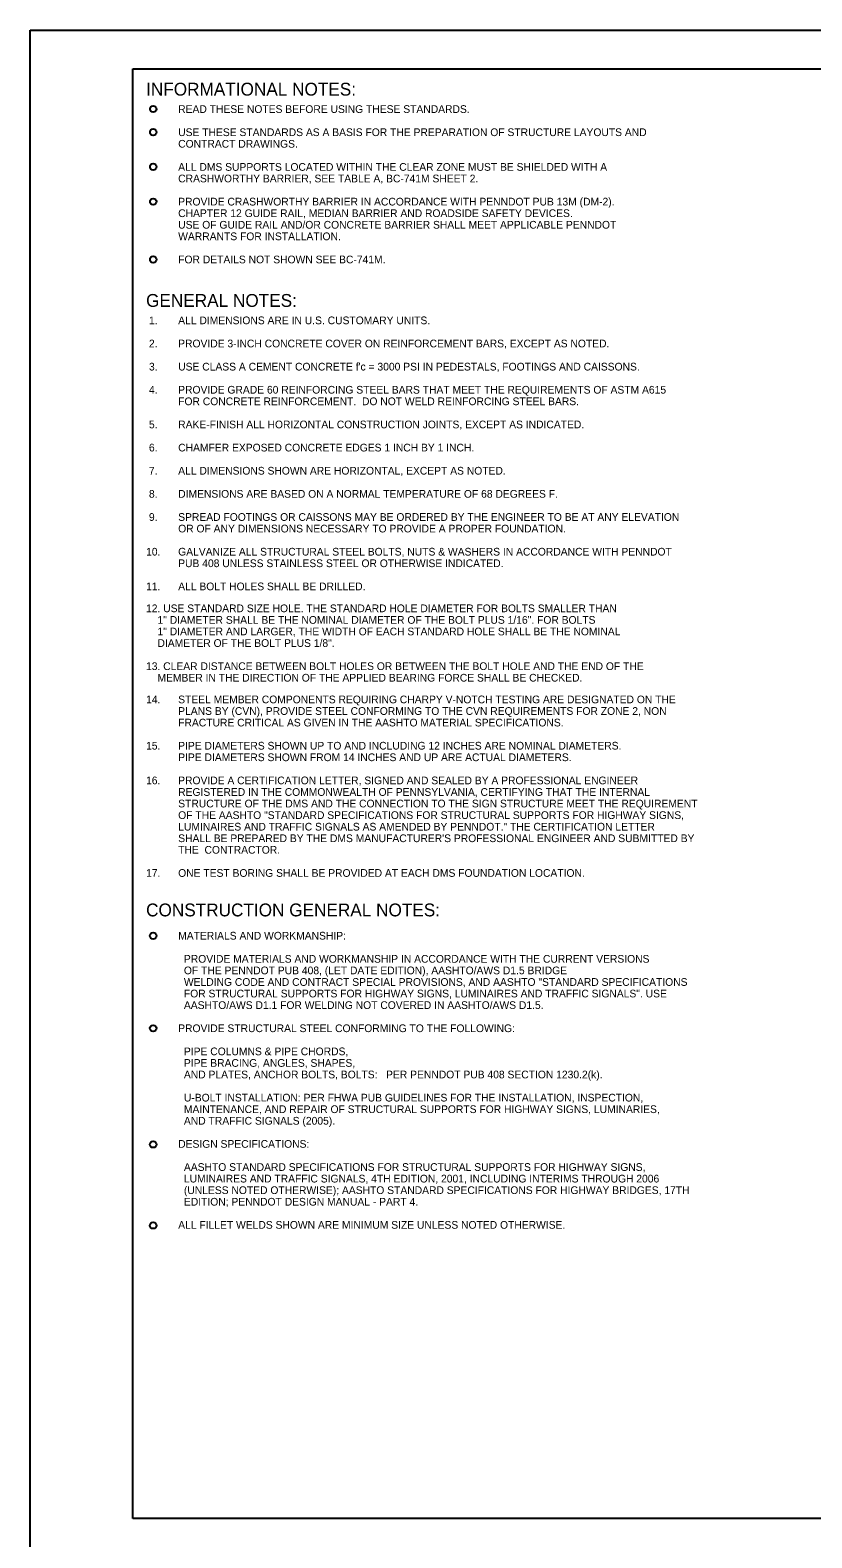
# Model space of a CAD drawing. Extents: x 3829340 to 3831660, y 499389 to 501171.
# Drawn here: x 3829340 to 3829644, y 500585 to 501171 of the extents above; entities that cross this region are included whole.
import ezdxf

# ---------------------------------------------------------------- set-up
doc = ezdxf.new("R2010")
doc.units = 0
for name, color, linetype in [('10', 7, 'Continuous'), ('2', 7, 'Continuous'), ('DIM TXT', 7, 'Continuous'), ('PLT-BNDY', 7, 'Continuous')]:
    doc.layers.add(name, color=color, linetype=linetype)

msp = doc.modelspace()

# ---------------------------------------------------------------- linework, layer by layer
at = {"layer": '2'}
for p, q in [((3829379.96, 500592.19), (3829379.96, 501156.19)), ((3829379.96, 501156.19), (3830165.96, 501156.19)), ((3830165.96, 500592.19), (3829379.96, 500592.19))]:
    msp.add_line(p, q, dxfattribs=at)
at = {"layer": 'DIM TXT'}
for centre in [(3829387.87, 501140.51), (3829387.87, 501131.51), (3829387.87, 501118.02), (3829387.87, 501104.48), (3829387.87, 501081.98), (3829387.86, 500818.89), (3829387.86, 500782.89), (3829387.86, 500737.73), (3829387.86, 500706.23)]:
    msp.add_circle(centre, 1.25, dxfattribs=at)
at = {"layer": 'PLT-BNDY'}
msp.add_lwpolyline([(3829339.96, 501171.19), (3830180.96, 501171.19), (3830180.96, 500577.19), (3829339.96, 500577.19)], close=True, dxfattribs=at)

# ---------------------------------------------------------------- texts
at = {"layer": '10'}
for s, p in [('12. USE STANDARD SIZE HOLE. THE STANDARD HOLE DIAMETER FOR BOLTS SMALLER THAN', (3829385.07, 500944.77)), ('    1" DIAMETER SHALL BE THE NOMINAL DIAMETER OF THE BOLT PLUS 1/16". FOR BOLTS', (3829385.07, 500940.27)), ('    1" DIAMETER AND LARGER, THE WIDTH OF EACH STANDARD HOLE SHALL BE THE NOMINAL', (3829385.07, 500935.77)), ('    DIAMETER OF THE BOLT PLUS 1/8".', (3829385.07, 500931.27)), ('13. CLEAR DISTANCE BETWEEN BOLT HOLES OR BETWEEN THE BOLT HOLE AND THE END OF THE', (3829385.07, 500922.27)), ('    MEMBER IN THE DIRECTION OF THE APPLIED BEARING FORCE SHALL BE CHECKED.', (3829385.07, 500917.77))]:
    msp.add_text(s, height=3, dxfattribs=at).set_placement(p)
at = {"layer": 'DIM TXT'}
for s, height, p in [('INFORMATIONAL NOTES:', 4.9999, (3829385.09, 501145.73)), ('READ THESE NOTES BEFORE USING THESE STANDARDS. ', 2.9999, (3829397.59, 501138.98)), ('USE THESE STANDARDS AS A BASIS FOR THE PREPARATION OF STRUCTURE LAYOUTS AND ', 2.9999, (3829397.59, 501129.98)), ('CONTRACT DRAWINGS. ', 2.9999, (3829397.59, 501125.48)), ('ALL DMS SUPPORTS LOCATED WITHIN THE CLEAR ZONE MUST BE SHIELDED WITH A ', 2.9999, (3829397.59, 501116.48)), ('CRASHWORTHY BARRIER, SEE TABLE A, BC-741M SHEET 2.', 2.9999, (3829397.59, 501111.98)), ('PROVIDE CRASHWORTHY BARRIER IN ACCORDANCE WITH PENNDOT PUB 13M (DM-2).', 2.9999, (3829397.59, 501102.98)), ('CHAPTER 12 GUIDE RAIL, MEDIAN BARRIER AND ROADSIDE SAFETY DEVICES. ', 2.9999, (3829397.59, 501098.48)), ('USE OF GUIDE RAIL AND/OR CONCRETE BARRIER SHALL MEET APPLICABLE PENNDOT', 2.9999, (3829397.59, 501093.98)), ('WARRANTS FOR INSTALLATION.', 2.9999, (3829397.59, 501089.48)), ('FOR DETAILS NOT SHOWN SEE BC-741M.', 2.9999, (3829397.59, 501080.48)), ('GENERAL NOTES:', 4.9999, (3829385.09, 501063.54)), (' 1.', 3, (3829385.09, 501056.79)), ('ALL DIMENSIONS ARE IN U.S. CUSTOMARY UNITS.', 2.9999, (3829397.59, 501056.79)), (' 2.', 3, (3829385.09, 501047.79)), ('PROVIDE 3-INCH CONCRETE COVER ON REINFORCEMENT BARS, EXCEPT AS NOTED.', 2.9999, (3829397.59, 501047.79)), (' 3.', 3, (3829385.09, 501038.79)), ("USE CLASS A CEMENT CONCRETE f'c = 3000 PSI IN PEDESTALS, FOOTINGS AND CAISSONS.", 2.9999, (3829397.59, 501038.79)), (' 4.', 3, (3829385.09, 501029.8)), ('PROVIDE GRADE 60 REINFORCING STEEL BARS THAT MEET THE REQUIREMENTS OF ASTM A615 ', 2.9999, (3829397.59, 501029.8)), ('FOR CONCRETE REINFORCEMENT.  DO NOT WELD REINFORCING STEEL BARS.', 2.9999, (3829397.59, 501025.3)), (' 5.', 3, (3829385.09, 501016.3)), ('RAKE-FINISH ALL HORIZONTAL CONSTRUCTION JOINTS, EXCEPT AS INDICATED.', 2.9999, (3829397.59, 501016.3)), (' 6.', 3, (3829385.09, 501007.3)), ('CHAMFER EXPOSED CONCRETE EDGES 1 INCH BY 1 INCH.', 2.9999, (3829397.59, 501007.3)), (' 7.', 3, (3829385.09, 500998.3)), ('ALL DIMENSIONS SHOWN ARE HORIZONTAL, EXCEPT AS NOTED.', 2.9999, (3829397.59, 500998.3)), (' 8.', 3, (3829385.09, 500989.3)), ('DIMENSIONS ARE BASED ON A NORMAL TEMPERATURE OF 68 DEGREES F.', 2.9999, (3829397.59, 500989.3)), (' 9.', 3, (3829385.09, 500980.3)), ('SPREAD FOOTINGS OR CAISSONS MAY BE ORDERED BY THE ENGINEER TO BE AT ANY ELEVATION ', 2.9999, (3829397.59, 500980.3)), ('OR OF ANY DIMENSIONS NECESSARY TO PROVIDE A PROPER FOUNDATION.', 2.9999, (3829397.59, 500975.8)), ('10.', 3, (3829385.09, 500966.8)), ('GALVANIZE ALL STRUCTURAL STEEL BOLTS, NUTS & WASHERS IN ACCORDANCE WITH PENNDOT ', 2.9999, (3829397.59, 500966.8)), ('PUB 408 UNLESS STAINLESS STEEL OR OTHERWISE INDICATED.', 2.9999, (3829397.59, 500962.3)), ('11.', 3, (3829385.09, 500953.3)), ('ALL BOLT HOLES SHALL BE DRILLED.', 2.9999, (3829397.59, 500953.3)), ('14.', 3, (3829385.09, 500909.33)), ('STEEL MEMBER COMPONENTS REQUIRING CHARPY V-NOTCH TESTING ARE DESIGNATED ON THE ', 2.9999, (3829397.59, 500909.33)), ('PLANS BY (CVN), PROVIDE STEEL CONFORMING TO THE CVN REQUIREMENTS FOR ZONE 2, NON ', 2.9999, (3829397.59, 500904.83)), ('FRACTURE CRITICAL AS GIVEN IN THE AASHTO MATERIAL SPECIFICATIONS.', 2.9999, (3829397.59, 500900.33)), ('15.', 3, (3829385.09, 500891.33)), ('PIPE DIAMETERS SHOWN UP TO AND INCLUDING 12 INCHES ARE NOMINAL DIAMETERS.', 2.9999, (3829397.59, 500891.33)), ('PIPE DIAMETERS SHOWN FROM 14 INCHES AND UP ARE ACTUAL DIAMETERS.', 2.9999, (3829397.59, 500886.83)), ('16.', 3, (3829385.09, 500877.83)), ('PROVIDE A CERTIFICATION LETTER, SIGNED AND SEALED BY A PROFESSIONAL ENGINEER ', 2.9999, (3829397.59, 500877.83)), ('STRUCTURE OF THE DMS AND THE CONNECTION TO THE SIGN STRUCTURE MEET THE REQUIREMENT ', 2.9999, (3829397.59, 500868.83)), ('REGISTERED IN THE COMMONWEALTH OF PENNSYLVANIA, CERTIFYING THAT THE INTERNAL ', 2.9999, (3829397.59, 500873.33)), ('OF THE AASHTO "STANDARD SPECIFICATIONS FOR STRUCTURAL SUPPORTS FOR HIGHWAY SIGNS,', 2.9999, (3829397.59, 500864.33)), ('LUMINAIRES AND TRAFFIC SIGNALS AS AMENDED BY PENNDOT." THE CERTIFICATION LETTER ', 2.9999, (3829397.59, 500859.83)), ('THE  CONTRACTOR.', 2.9999, (3829397.59, 500850.83)), ("SHALL BE PREPARED BY THE DMS MANUFACTURER'S PROFESSIONAL ENGINEER AND SUBMITTED BY ", 2.9999, (3829397.59, 500855.33)), ('17.', 3, (3829385.09, 500841.83)), ('ONE TEST BORING SHALL BE PROVIDED AT EACH DMS FOUNDATION LOCATION.', 2.9999, (3829397.59, 500841.83)), ('CONSTRUCTION GENERAL NOTES:', 4.9999, (3829385.09, 500826.44)), ('MATERIALS AND WORKMANSHIP:', 2.9999, (3829397.59, 500817.42)), ('  OF THE PENNDOT PUB 408, (LET DATE EDITION), AASHTO/AWS D1.5 BRIDGE', 2.9999, (3829397.59, 500803.92)), ('  PROVIDE MATERIALS AND WORKMANSHIP IN ACCORDANCE WITH THE CURRENT VERSIONS ', 2.9999, (3829397.59, 500808.42)), ('  WELDING CODE AND CONTRACT SPECIAL PROVISIONS, AND AASHTO "STANDARD SPECIFICATIONS', 2.9999, (3829397.59, 500799.42)), ('  FOR STRUCTURAL SUPPORTS FOR HIGHWAY SIGNS, LUMINAIRES AND TRAFFIC SIGNALS". USE', 2.9999, (3829397.59, 500794.92)), ('  AASHTO/AWS D1.1 FOR WELDING NOT COVERED IN AASHTO/AWS D1.5.', 2.9999, (3829397.59, 500790.42)), ('PROVIDE STRUCTURAL STEEL CONFORMING TO THE FOLLOWING:', 2.9999, (3829397.59, 500781.42)), ('  PIPE COLUMNS & PIPE CHORDS,', 2.9999, (3829397.59, 500772.42)), ('  AND PLATES, ANCHOR BOLTS, BOLTS:   PER PENNDOT PUB 408 SECTION 1230.2(k).', 2.9999, (3829397.59, 500763.43)), ('  PIPE BRACING, ANGLES, SHAPES,', 2.9999, (3829397.59, 500767.93)), ('  U-BOLT INSTALLATION: PER FHWA PUB GUIDELINES FOR THE INSTALLATION, INSPECTION,', 2.9999, (3829397.59, 500754.43)), ('  AND TRAFFIC SIGNALS (2005).', 2.9999, (3829397.59, 500745.43)), ('  MAINTENANCE, AND REPAIR OF STRUCTURAL SUPPORTS FOR HIGHWAY SIGNS, LUMINARIES,', 2.9999, (3829397.59, 500749.93)), ('DESIGN SPECIFICATIONS:', 2.9999, (3829397.59, 500736.43)), ('  AASHTO STANDARD SPECIFICATIONS FOR STRUCTURAL SUPPORTS FOR HIGHWAY SIGNS,', 2.9999, (3829397.59, 500727.43)), ('  LUMINAIRES AND TRAFFIC SIGNALS, 4TH EDITION, 2001, INCLUDING INTERIMS THROUGH 2006', 2.9999, (3829397.59, 500722.93)), ('  (UNLESS NOTED OTHERWISE); AASHTO STANDARD SPECIFICATIONS FOR HIGHWAY BRIDGES, 17TH', 2.9999, (3829397.59, 500718.43)), ('  EDITION; PENNDOT DESIGN MANUAL - PART 4.', 2.9999, (3829397.59, 500713.93)), ('ALL FILLET WELDS SHOWN ARE MINIMUM SIZE UNLESS NOTED OTHERWISE.', 2.9999, (3829397.59, 500704.93))]:
    msp.add_text(s, height=height, dxfattribs=at).set_placement(p)

doc.saveas('drawing.dxf')
